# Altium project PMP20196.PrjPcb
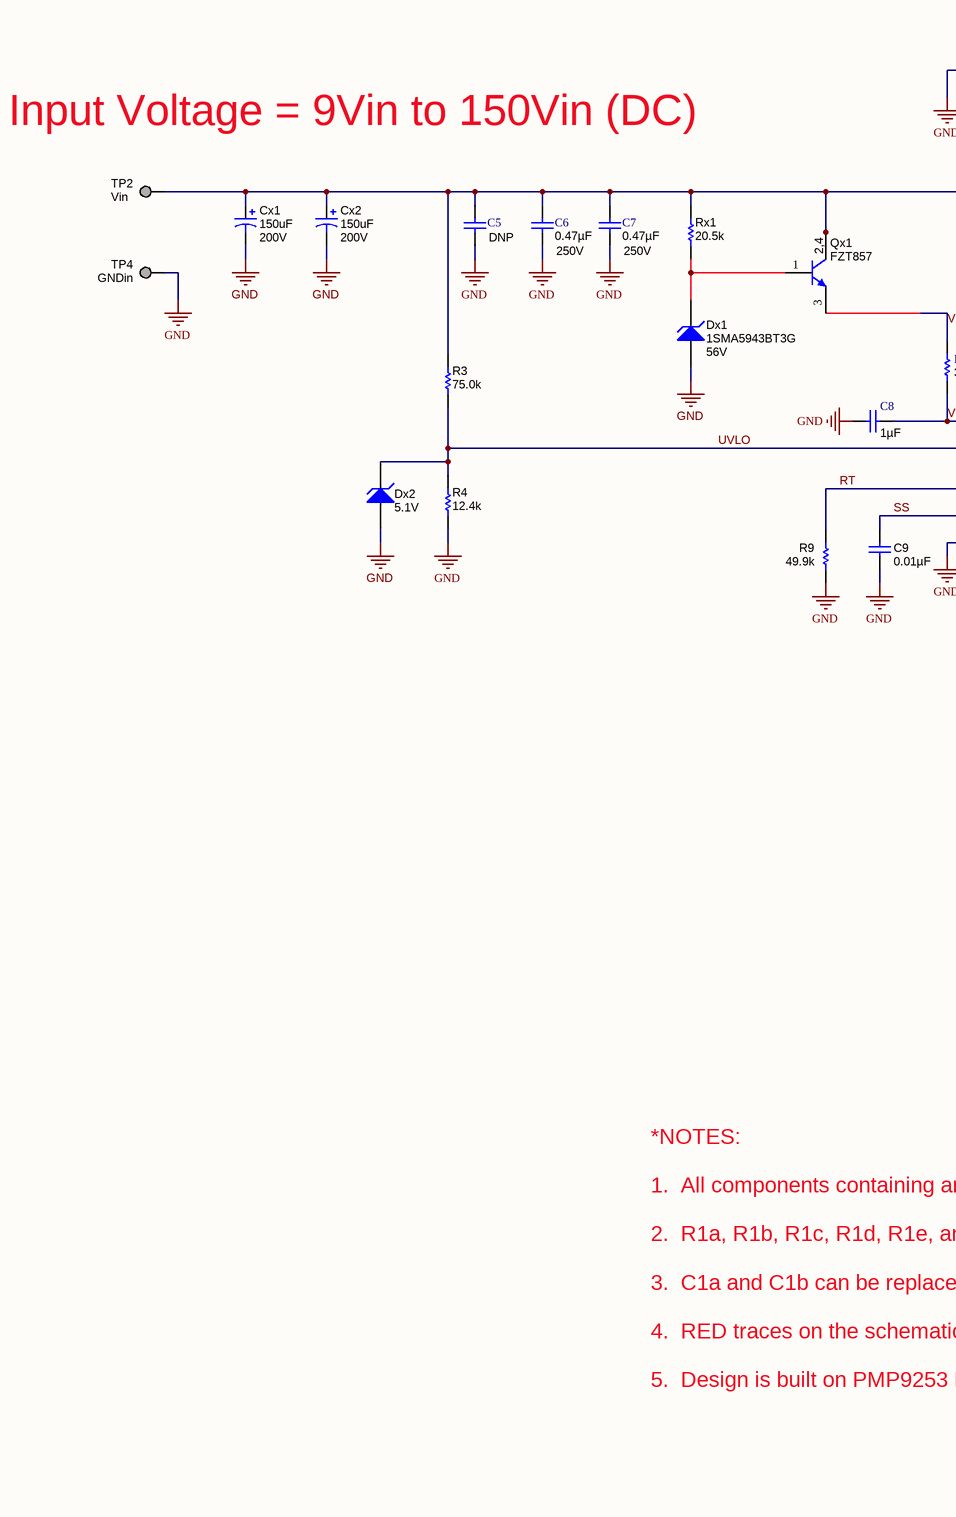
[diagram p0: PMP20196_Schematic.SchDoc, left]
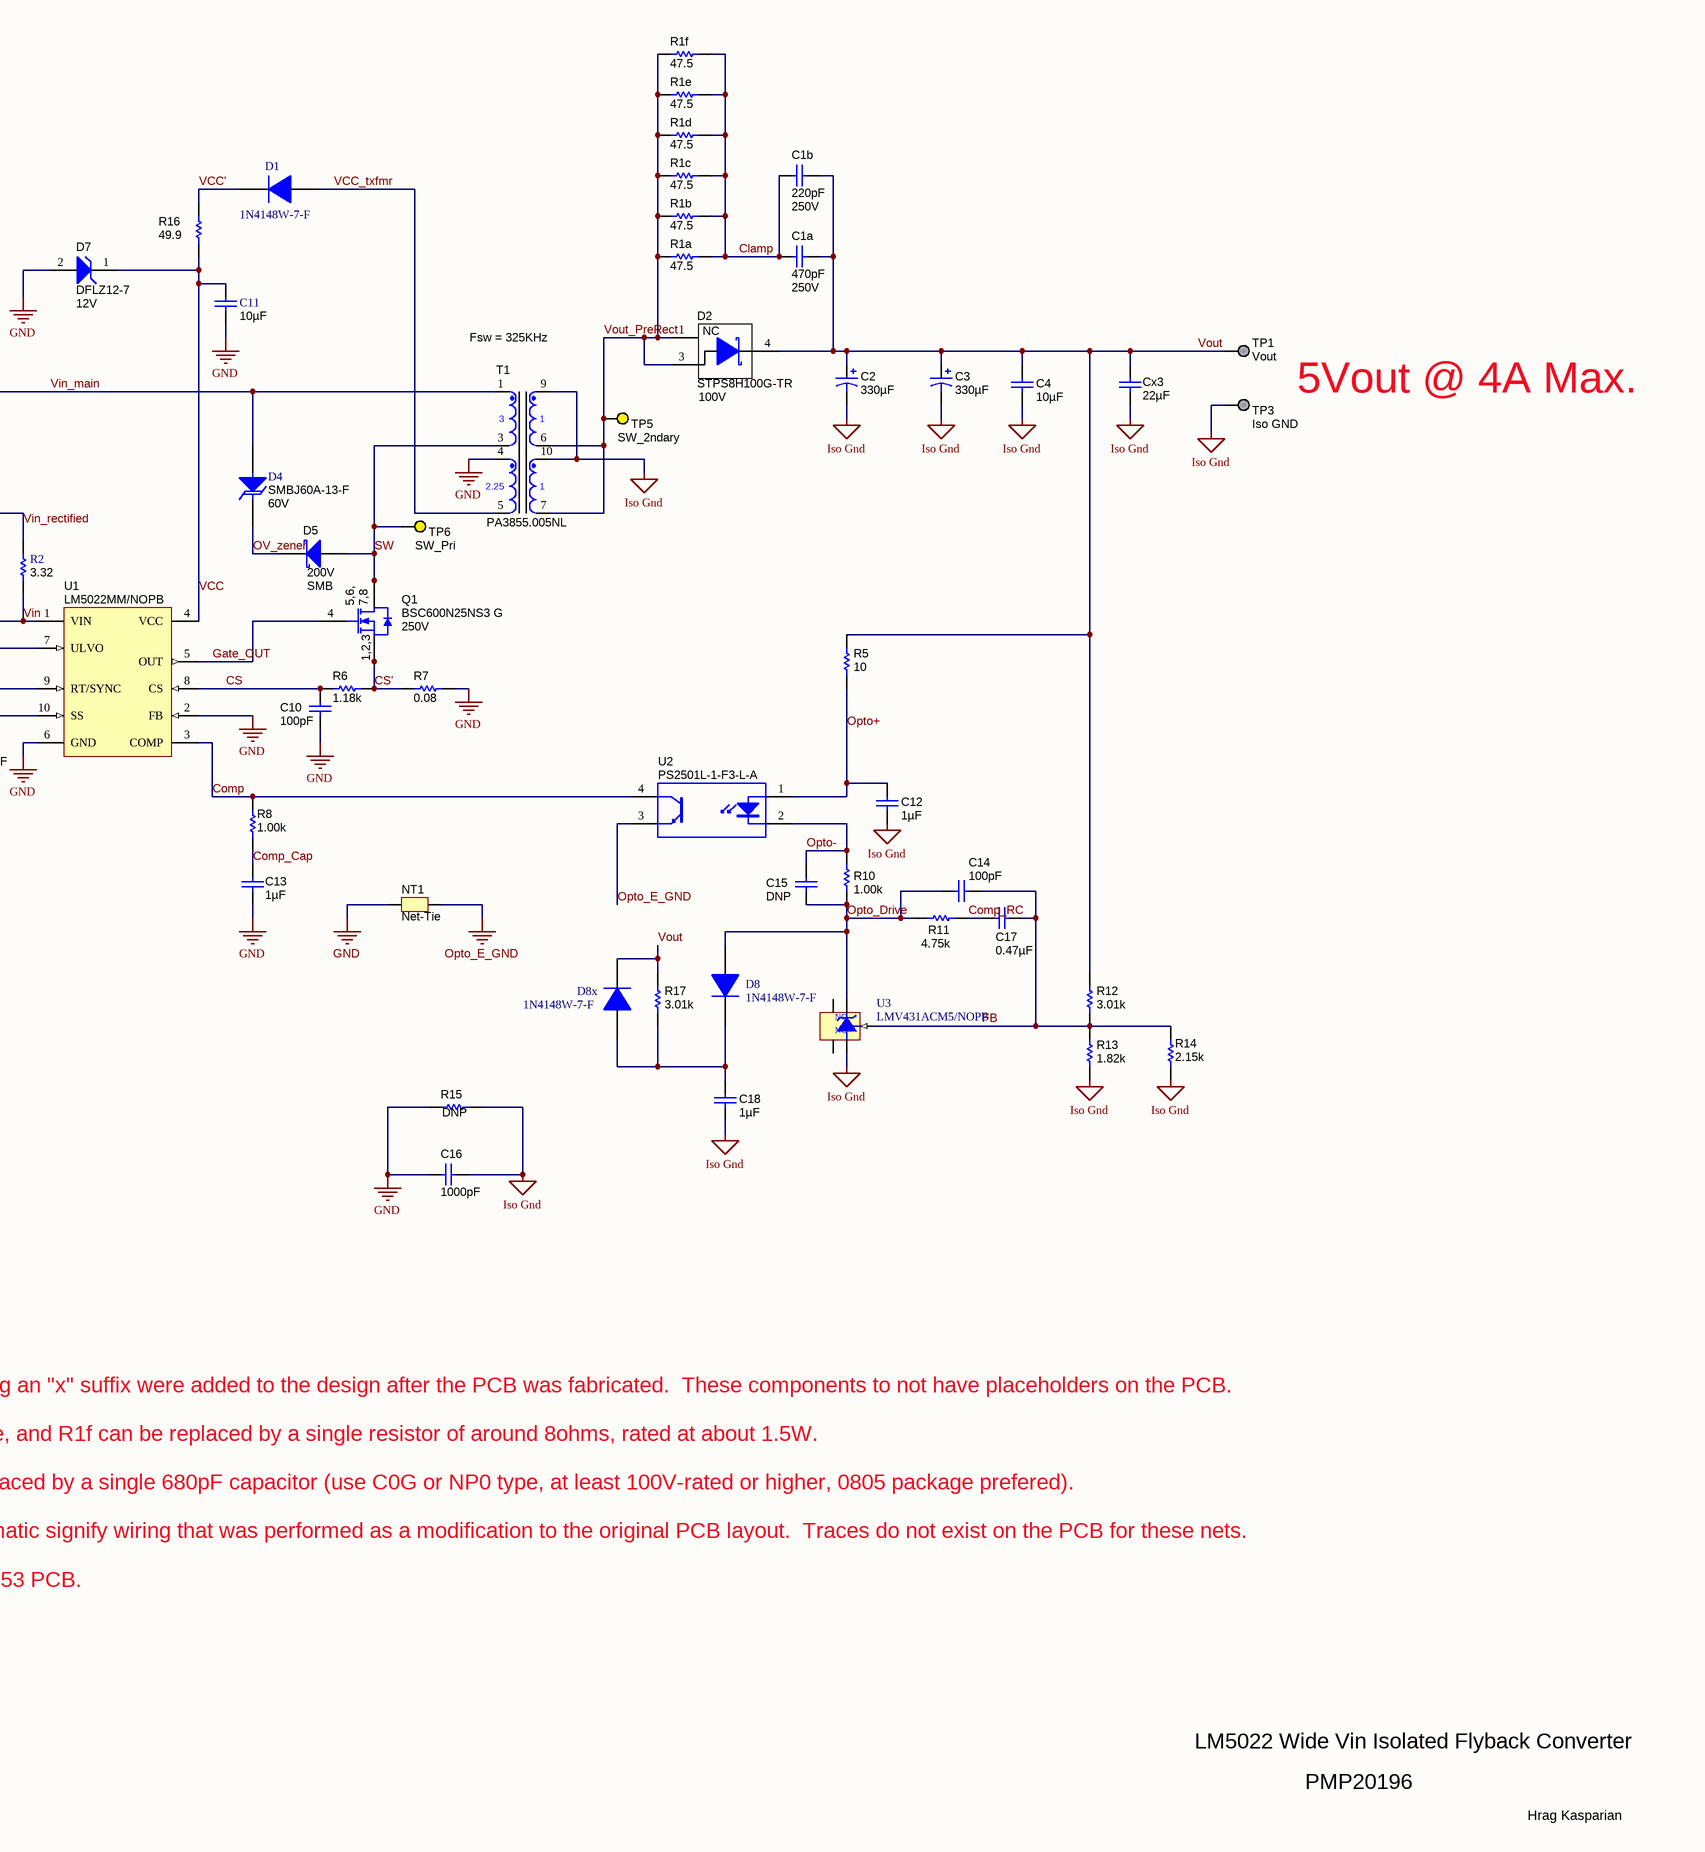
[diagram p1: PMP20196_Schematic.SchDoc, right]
TID: PMP20196; TechSupport: http://www.ti.com/support; SCH_Rev: A; PRJ_Title: LM5022 Isolated Flyback Converter; PRJ_Number: PMP20196; PRJ_Engineer: Hrag Kasparian; CopyrightYear: 2016
2 sheets, 82 parts. Net scope: global (net labels, ports and power ports of the same name join across sheets).
Board file: PMP9253.PcbDoc
Sheets:
  PMP20196_Schematic.SchDoc
  PMP20196_EVM_Hardware.SchDoc

## Sheet PMP20196_Schematic.SchDoc: Schematic
size C; DocumentNumber: 1; SheetNumber: 1; SheetTotal: 2; PageSetup: Record=PageOptions¦CenterHorizontal=True¦CenterVertical=True¦PrintScale=0.70¦XCorrection=1.00¦YCorrection=1.00¦PrintKind=1¦BorderSize=5000000¦LeftOffset=0¦BottomOffset=0¦Orientation=2¦PaperLength=1000¦PaperWidth=1000¦Scale=100¦PaperSource=15¦PrintQuality=600¦MediaType=1¦DitherType=10¦PaperKind=11x17¦PrintScaleMode=1

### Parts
C1a  value 470pF  Value1: 250V  [0603_HV]  (hidden comment: CGA3E3C0G2E471J)
C1b  value 220pF  Value1: 250V  [0603_HV]  (hidden comment: CGA3E3C0G2E471J)
C2  ValueDisplayed: 330µF  [SM_RADIAL_8MM]  (hidden comment: Santo, 10SVP330M)
C3  ValueDisplayed: 330µF  [SM_RADIAL_8MM]  (hidden comment: Santo, 10SVP330M)
C4  ValueDisplayed: 10µF  [0805_HV]  (hidden comment: GRM21BR71A106KE51L)
C5  DNP  [1812]
C6  ValueDisplayed: 0.47µF  Value2: 250V  [1812]  (hidden comment: GRM43DR72E474KW01L)
C7  ValueDisplayed: 0.47µF  Value2: 250V  [1812]  (hidden comment: GRM43DR72E474KW01L)
C8  ValueDisplayed: 1µF  [1206]  (hidden comment: C3216X7R2A105M)
C9  ValueDisplayed: 0.01µF  [0603]  (hidden comment: C1608C0G1E103J)
C10  ValueDisplayed: 100pF  [0603]  (hidden comment: 06035A101JAT2A)
C11  ValueDisplayed: 10µF  [1206]  (hidden comment: GRM31CR71E106KA12L)
C12  ValueDisplayed: 1µF  [0603]  (hidden comment: C1608X7R1C105K)
C13  ValueDisplayed: 1µF  [0603]  (hidden comment: C1608X7R1E105K080AB)
C14  ValueDisplayed: 100pF  [0603]  (hidden comment: 06033C101KAT2A)
C15  DNP  [0603]
C16  ValueDisplayed: 1000pF  [0805_HV]  (hidden comment: C2012C0G2E102J)
C17  ValueDisplayed: 0.47µF  [0603]  (hidden comment: GRM188R61A474KA61D)
C18  ValueDisplayed: 1µF  [0603]  (hidden comment: C1608X7R1C105K)
Cx1  value 150uF  Value1: 200V  [TBD]  (hidden comment: EEU-EE2D151)
Cx2  value 150uF  Value1: 200V  [TBD]  (hidden comment: EEU-EE2D151)
Cx3  ValueDisplayed: 22µF  [1210_280]  (hidden comment: CGA6P1X7R1C226M250AC)
D1  1N4148W-7-F  [SOD-123]
D2  STPS8H100G-TR  value 100V  [DDPAK]
D4  SMBJ60A-13-F  value 60V  [SMB]
D5  200V  [SMB]
D7  DFLZ12-7  value 12V  [powerDI123]
D8  1N4148W-7-F  [SOD-123]
D8x  1N4148W-7-F  [SOD-123]
Dx1  1SMA5943BT3G  value 56V  [SMA]
Dx2  value 5.1V  [TBD]  (hidden comment: DZ2J051M0L)
NT1  Net-Tie  [Net-Tie_10mil]  (net tie, no BOM)
Q1  BSC600N25NS3 G  value 250V  [PG-TDSON-8]
Qx1  FZT857  [SOT-223]
R1a  ValueDisplayed: 47.5  [1206]  (hidden comment: CRCW120647R5FKEA)
R1b  ValueDisplayed: 47.5  [1206]  (hidden comment: CRCW120647R5FKEA)
R1c  ValueDisplayed: 47.5  [1206]  (hidden comment: CRCW120647R5FKEA)
R1d  ValueDisplayed: 47.5  [1206]  (hidden comment: CRCW120647R5FKEA)
R1e  ValueDisplayed: 47.5  [1206]  (hidden comment: CRCW120647R5FKEA)
R1f  ValueDisplayed: 47.5  [1206]  (hidden comment: CRCW120647R5FKEA)
R2  value 3.32  [1206]  (hidden comment: CRCW12063R32FKEA)
R3  ValueDisplayed: 75.0k  [1206]  (hidden comment: CRCW120675K0FKEA)
R4  ValueDisplayed: 12.4k  [0603]  (hidden comment: CRCW060312K4FKEA)
R5  10  [0805_HV]
R6  ValueDisplayed: 1.18k  [0603]  (hidden comment: CRCW06031K18FKEA)
R7  ValueDisplayed: 0.08  [2512]  (hidden comment: CRA2512-FZ-R080ELF)
R8  value 1.00k  [0603]  (hidden comment: CRCW06031K00FKEA)
R9  value 49.9k  [0603]  (hidden comment: CRCW060349K9FKEA)
R10  value 1.00k  [0603]  (hidden comment: CRCW06031K00FKEA)
R11  value 4.75k  [0603]  (hidden comment: CRCW06034K75FKEA)
R12  value 3.01k  [0603]  (hidden comment: CRCW06033K01FKEA)
R13  value 1.82k  [0603]  (hidden comment: CRCW06031K82FKEA)
R14  ValueDisplayed: 2.15k  [0603]  (hidden comment: CRCW06032K15FKEA)
R15  DNP  [0805_HV]
R16  value 49.9  [1206]  (hidden comment: CRCW120649R9FKEA)
R17  value 3.01k  [0603]  (hidden comment: CRCW06033K01FKEA)
Rx1  ValueDisplayed: 20.5k  [2512]  (hidden comment: CRCW251220K5FKEG)
T1  PA3855.005NL  [PA3855.005NL]
TP1  Vout  [Keystone1503-2]
TP2  Vin  [Keystone1503-2]
TP3  Iso GND  [Keystone1503-2]
TP4  GNDin  [Keystone1503-2]
TP5  SW_2ndary  [Keystone5014]
TP6  SW_Pri  [Keystone5014]
U1  LM5022MM/NOPB  [MUB10A_N]
U2  PS2501L-1-F3-L-A  [PS2501L]
U3  LMV431ACM5/NOPB  [MF05A_N]

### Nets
GND: C5.2 C6.2 C7.2 C8.2 C9.2 C10.2 C11.2 C13.2 C16.2 Cx1.2(-) Cx2.2(-) D7.2(A) Dx1.2(A) Dx2.2(A) NT1.1 R4.1 R7.2 R9.1 R15.1 T1.4 TP4.1 U1.2(FB) U1.6(GND)
Iso Gnd: C2.2(-) C3.2(-) C4.2 C12.1 C16.1 C18.1 Cx3.1 R13.1 R14.1 R15.2 T1.9 T1.10 TP3.1 U3.5(A)
Opto_E_GND: NT1.2 U2.3(E)
Clamp: C1a.1 C1b.1 R1a.2 R1b.2 R1c.2 R1d.2 R1e.2 R1f.2
Comp: R8.2 U1.3(COMP) U2.4(C)
Comp_Cap: C13.1 R8.1
Comp_RC: C17.2 R11.2
CS: C10.1 R6.1 U1.8(CS)
CS': Q1.1(S) Q1.2(S) Q1.3(S) R6.2 R7.1
FB: C14.1 C17.1 R12.1 R13.2 R14.2 U3.4(REF)
Gate_OUT: Q1.4(G) U1.5(OUT)
Opto+: C12.2 R5.1 U2.1(A)
Opto-: C15.2 R10.2 U2.2(K)
Opto_Drive: C14.2 C15.1 D8.2(A) R10.1 R11.1 U3.3(K)
OV_zener: D4.1(K) D5.1(K)
RT: R9.2 U1.9(RT/SYNC)
SS: C9.1 U1.10(SS)
SW: D5.2(A) Q1.5(D) Q1.6(D) Q1.7(D) Q1.8(D) Q1.9(D) T1.3 TP6.1
UVLO: Dx2.1(K) R3.1 R4.2 U1.7(ULVO)
VCC: C11.1 D7.1(K) R16.1 U1.4(VCC)
VCC': D1.1(K) R16.2
VCC_txfmr: D1.2(A) T1.5
Vin: C8.1 R2.1 U1.1(VIN)
Vin_main: C5.1 C6.1 C7.1 Cx1.1(+) Cx2.1(+) D4.2(A) Qx1.2(C) Qx1.4(C) R3.2 Rx1.2 T1.1 TP2.1
Vin_rectified: Qx1.3(E) R2.2
Vout: C1a.2 C1b.2 C2.1(+) C3.1(+) C4.1 Cx3.2 D2.4(K) D8x.1(K) R5.2 R12.2 R17.2 TP1.1
Vout_PreRect: D2.1(NC) D2.3(A) R1a.1 R1b.1 R1c.1 R1d.1 R1e.1 R1f.1 T1.6 T1.7 TP5.1
NetC18_2: C18.2 D8.1(K) D8x.2(A) R17.1
NetDx1_1: Dx1.1(K) Qx1.1(B) Rx1.1

Not connected (* = marked no-connect by the designer): U3 1(NC) 2(NC)

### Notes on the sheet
- Input Voltage = 9Vin to 150Vin (DC)
- (near T1) Fsw = 325KHz
- 5Vout @ 4A Max.
- *NOTES:
  1.  All components containing an "x" suffix were added to the design after the PCB was fabricated.  These components to not have placeholders on the PCB.
  2.  R1a, R1b, R1c, R1d, R1e, and R1f can be replaced by a single resistor of around 8ohms, rated at about 1.5W.
  3.  C1a and C1b can be replaced by a single 680pF capacitor (use C0G or NP0 type, at least 100V-rated or higher, 0805 package prefered).
  4.  RED traces on the schematic signify wiring that was performed as a modification to the original PCB layout.  Traces do not exist on the PCB for these nets.
  5.  Design is built on PMP9253 PCB.
- LM5022 Wide Vin Isolated Flyback Converter
- PMP20196
- Hrag Kasparian

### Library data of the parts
C1a = Capacitor: CAP, CERM, 470pF, 250V, C0G, 5%, 0603; Manufacturer: TDK; Polarized: N; U/M: EA
C1b = Capacitor: CAP, CERM, 220pF, 250V, C0G, 5%, 0603; Manufacturer: TDK; Polarized: N; U/M: EA
C2 C3 = 10SVP330M: CAP, OS-CON, 330uF, 10V, +/-20%, 0.017 ohm, 8x10 SMD; Manufacturer: Sanyo; Polarized: Y; CompType: Capacitor; U/M: EA; Cap_F: 0.00033; Tolerance_%: 20; VDC_V: 10; ESR_Ohm: 0.017; IRMS_A: 3.95; TaMin_C: -55; TaMax_C: 105; Cap_Case: 8.3x8.3x11.9
C4 = GRM21BR71A106KE51L: CAP, CERM, 10uF, 10V, +/-10%, X7R, 0805; Manufacturer: MuRata; Polarized: N; CompType: Capacitor; U/M: EA; Cap_F: 0.00001; Tolerance_%: 10; ESR_Ohm: 0.003; Value1: 0.003 ohm; TaMin_C: -55; TaMax_C: 125; Cap_Case: 0805
C5 = GRM43DR72E474KW01L: CAP, CERM, 0.47 µF, 250 V, +/- 10%, X7R, 1812; Manufacturer: MuRata; Polarized: N; TaMax_C: 125; TaMin_C: -55; Tolerance_%: 10; VDC_V: 250; Cap_F: 0.00000047; CompType: Capacitor; Value: 0.47uF; ValueDisplayed: 0.47µF; U/M: EA; Value1: Unknown; Value2: 250V; AEC Category: Q200
C6 C7 = GRM43DR72E474KW01L: CAP, CERM, 0.47 µF, 250 V, +/- 10%, X7R, 1812; Manufacturer: MuRata; Polarized: N; TaMax_C: 125; TaMin_C: -55; Tolerance_%: 10; VDC_V: 250; Cap_F: 0.00000047; CompType: Capacitor; Value: 0.47uF; U/M: EA; Value1: Unknown; AEC Category: Q200
C8 = C3216X7R2A105M: CAP, CERM, 1uF, 100V, +/-20%, C Series, 1206; Manufacturer: TDK; ESR_Ohm: 0.006; IRMS_A: 4.5; Polarized: N; TaMax_C: 125; TaMin_C: -55; Tolerance_%: 20; VDC_V: 100; Cap_F: 0.000001; CompType: Capacitor; U/M: EA; Value1: 0.006 ohm
C9 = C1608C0G1E103J: CAP, CERM, 0.01uF, 25V, +/-5%, C0G/NP0, 0603; Manufacturer: TDK; Polarized: N; CompType: Capacitor; U/M: EA; Cap_F: 0.00000001; Tolerance_%: 5; Value1: Unknown; VDC_V: 25; TaMin_C: -55; TaMax_C: 125
C10 = 06035A101JAT2A: CAP, CERM, 100pF, 50V, +/-5%, C0G/NP0, 0603; Manufacturer: AVX; Polarized: N; CompType: Capacitor; U/M: EA; Cap_F: 0.0000000001; Tolerance_%: 5; ESR_Ohm: 0.119; Value1: 0.119 ohm; VDC_V: 50; TaMin_C: -55; TaMax_C: 125
C11 = GRM31CR71E106KA12L: CAP, CERM, 10uF, 25V, +/-10%, X7R, 1206; Manufacturer: MuRata; Cap_Case: 2220; Polarized: N; TaMax_C: 125; TaMin_C: -55; Tolerance_%: 10; VDC_V: 25; Cap_F: 0.00001; CompType: Capacitor; U/M: EA; Value1: Unknown
C12 C18 = C1608X7R1C105K: CAP, CERM, 1uF, 16V, +/-10%, X7R, 0603; Manufacturer: TDK; Polarized: N; CompType: Capacitor; U/M: EA; Cap_F: 0.000001; Tolerance_%: 10; ESR_Ohm: 0.0057; Value1: 0.0057 ohm; VDC_V: 16; TaMin_C: -55; TaMax_C: 125
C13 = C1608X7R1E105K080AB: CAP, CERM, 1uF, 25V, +/-10%, X7R, 0603; Manufacturer: TDK; Polarized: N; CompType: Capacitor; U/M: EA; Cap_F: 0.000001; Tolerance_%: 10; Value1: Unknown; VDC_V: 25; TaMin_C: -55; TaMax_C: 125
C14 = 06033C101KAT2A: CAP, CERM, 100pF, 25V, +/-10%, X7R, 0603; Manufacturer: AVX; Polarized: N; CompType: Capacitor; U/M: EA; Cap_F: 0.0000000001; Tolerance_%: 10; Value1: Unknown; VDC_V: 25; TaMin_C: -55; TaMax_C: 125
C15 = C1608X7R1C105K: CAP, CERM, 1uF, 16V, +/-10%, X7R, 0603; Manufacturer: TDK; Polarized: N; CompType: Capacitor; ValueDisplayed: 1µF; U/M: EA; Cap_F: 0.000001; Tolerance_%: 10; ESR_Ohm: 0.0057; Value1: 0.0057 ohm; VDC_V: 16; TaMin_C: -55; TaMax_C: 125
C16 = C2012C0G2E102J: CAP, CERM, 1000pF, 250V, +/-5%, C0G/NP0, 0805; Manufacturer: TDK; Polarized: N; CompType: Capacitor; U/M: EA; Cap_F: 0.000000001; Tolerance_%: 5; ESR_Ohm: 0.0408; Value1: 0.0408 ohm; VDC_V: 250; TaMin_C: -55; TaMax_C: 125; Cap_Case: 0805
C17 = GRM188R61A474KA61D: CAP, CERM, 0.47uF, 10V, +/-10%, X5R, 0603; Manufacturer: MuRata; Polarized: N; CompType: Capacitor; U/M: EA; Cap_F: 0.00000047; Tolerance_%: 10; Value1: Unknown; TaMin_C: -55; TaMax_C: 85
Cx1 Cx2 = Capacitor_Polarized: CAP, Al Electrolytic, 150uF, 200V, +/-20%, 1.86Arms, TH; Manufacturer: Panasonic; Polarized: Y; U/M: EA
Cx3 = CGA6P1X7R1C226M250AC: CAP, CERM, 22 µF, 16 V, +/- 20%, X7R, AEC-Q200 Grade 1, 1210; Manufacturer: TDK; Polarized: N; CompType: Capacitor; Value: 22uF; U/M: EA; Cap_F: 0.000022; Tolerance_%: 20; Value1: Unknown; VDC_V: 16; Value2: 16V; TaMin_C: -55; TaMax_C: 125; Cap_Case: 1210; AEC Category: Q200; AEC Qualified: Y; AEC Grade: 1
D1 D8 D8x = 1N4148W-7-F: Diode, Ultrafast, 100V, 0.15A, SOD-123; Manufacturer: Diodes Inc.; U/M: EA; Vf_V: 1.25; Io_A: 0.15; Vr_V: 100; TJmax_C: 150; Value: 1.25V
D2 = Diode_Schottky_A3C4: Diode, Schottky, 100V, 8A, D2PAK; Manufacturer: ST Microelectronics; U/M: EA
D4 = SMBJ60A-13-F: Diode, TVS, Uni, 60 V, 600 W, SMB; Manufacturer: Diodes Inc.; U/M: EA; Power_W: 5; Value1: 5W; Vr_V: 60; AEC Category: Q101
D5 = MBRS3200T3G: Diode, Schottky, 200 V, 3 A, SMB; Manufacturer: ON Semiconductor; U/M: EA; Vf_V: 0.84; Value1: 3A; Value2: 0.84V; Io_A: 3; Vr_V: 200; TJmax_C: 175; RJC_CperW: 62; AEC Category: Q101
D7 = DFLZ12-7: Diode, Zener, 12V, 1W, PowerDI123; Manufacturer: Diodes Inc.; U/M: EA; Power_W: 1; Vz_V: 12; RJA_CperW: 110
Dx1 = Zener: Diode, Zener, 56V, 1.5W, SMA; Manufacturer: ON Semi; SymbolCreator: a0412235; U/M: EA
Dx2 = Zener: Diode, Zener, 5.1V, 200mW, +/-5%, SOD-323F; Manufacturer: Panasonic; SymbolCreator: a0412235; U/M: EA
NT1 = Net-Tie: Single point connection between nets.; SymbolCreator: codlsc
Q1 = BSC600N25NS3 G: MOSFET, N-CH, 250 V, 25 A, PG-TDSON-8; Manufacturer: Infineon Technologies; Alternate Manufacturer: None; U/M: EA; ChType: N; VdsMax_V: 250; Value1: 0.06 ohm; Rdson45_ohm: 0.06; Value2: 22 nC; QgTyp_nC: 22; Vgs_V: 20; IdsMax_A: 25; AEC Category: Q101
Qx1 = FZT857, Zetex: Transistor, NPN, 300 V, 3.5 A, SOT-223; Manufacturer: Zetex; SymbolCreator: a0412235; PNP: 0; NPN: 1; Vceo_V: 300; Vcesat1_V: 0.095; Value: 300 V; IcRated_A: 3.5; Value1: 3.5 A; HfeMax: 200; TaMin_C: -55; TaMax_C: 150; CompType: BJT; U/M: EA; AEC Category: Q101
R1a R1b R1c R1d R1e R1f = CRCW120647R5FKEA: RES, 47.5, 1%, 0.25 W, 1206; Manufacturer: Vishay-Dale; CompType: Resistor; Value: 47.5; Value_Code: 47R5; Tolerance_%: 1; Power_W: 0.25; Value2: 0.25W; VDC_V: 200; TempCo: 100 ppm/C; EIA_Code: E96; U/M: EA; AEC Category: Q200
R2 = CRCW12063R32FKEA: RES, 3.32 ohm, 1%, 0.25W, 1206; Manufacturer: Vishay-Dale; CompType: Resistor; Tolerance_%: 1; VDC_V: 200; Power_W: 0.25; Value_Code: 3R32; TempCo_ppm/C: 100; EIA_Code: E96; U/M: EA
R3 = CRCW120675K0FKEA: RES, 75.0 k, 1%, 0.25 W, 1206; Manufacturer: Vishay-Dale; CompType: Resistor; Value: 75.0k; Res_ohm: 75000; Value_Code: 75k0; Tolerance_%: 1; Power_W: 0.25; Value2: 0.25W; VDC_V: 200; TempCo: 100 ppm/C; EIA_Code: E96; U/M: EA; AEC Category: Q200
R4 = CRCW060312K4FKEA: RES, 12.4 k, 1%, 0.1 W, 0603; Manufacturer: Vishay-Dale; CompType: Resistor; Value: 12.4k; Res_ohm: 12400; Value_Code: 12k4; Tolerance_%: 1; Power_W: 0.1; Value2: 0.1W; VDC_V: 75; TempCo: 100 ppm/C; EIA_Code: E96; U/M: EA; AEC Category: Q200
R5 = CRCW080510R0JNEA: RES, 10 ohm, 5%, 0.125W, 0805; Manufacturer: Vishay-Dale; CompType: Resistor; Value_Code: 10R0; Tolerance_%: 5; Power_W: 0.125; VDC_V: 150; TempCo: 200 ppm/C; EIA_Code: E24; U/M: EA
R6 = CRCW06031K18FKEA: RES, 1.18 k, 1%, 0.1 W, 0603; Manufacturer: Vishay-Dale; CompType: Resistor; Res_ohm: 1180; Value_Code: 1k18; Tolerance_%: 1; Power_W: 0.1; Value2: 0.1W; VDC_V: 75; TempCo: 100 ppm/C; EIA_Code: E96; U/M: EA; Value: 1.18k; AEC Category: Q200
R7 = CRA2512-FZ-R080ELF: RES, 0.08, 1%, 3 W, 2512; Manufacturer: Bourns; CompType: Resistor; Value: 0.08; U/M: EA; Value_Code: R080; Tolerance_%: 1; Power_W: 3; Value2: 3W; VDC_V: 0; TempCo: 75 ppm/C; AEC Category: Q200
R8 R10 = CRCW06031K00FKEA: RES, 1.00k ohm, 1%, 0.1W, 0603; Manufacturer: Vishay-Dale; CompType: Resistor; Res_ohm: 1000; Value_Code: 1k00; Tolerance_%: 1; Power_W: 0.1; VDC_V: 75; TempCo: 100 ppm/C; EIA_Code: E96; U/M: EA
R9 = CRCW060349K9FKEA: RES, 49.9k ohm, 1%, 0.1W, 0603; Manufacturer: Vishay-Dale; CompType: Resistor; Res_ohm: 49900; Value_Code: 49k9; Tolerance_%: 1; Power_W: 0.1; VDC_V: 75; TempCo: 100 ppm/C; EIA_Code: E96; U/M: EA
R11 = CRCW06034K75FKEA: RES, 4.75k ohm, 1%, 0.1W, 0603; Manufacturer: Vishay-Dale; CompType: Resistor; Res_ohm: 4750; Value_Code: 4k75; Tolerance_%: 1; Power_W: 0.1; VDC_V: 75; TempCo: 100 ppm/C; EIA_Code: E96; U/M: EA
R12 R17 = CRCW06033K01FKEA: RES, 3.01k ohm, 1%, 0.1W, 0603; Manufacturer: Vishay-Dale; CompType: Resistor; Res_ohm: 3010; Value_Code: 3k01; Tolerance_%: 1; Power_W: 0.1; VDC_V: 75; TempCo: 100 ppm/C; EIA_Code: E96; U/M: EA
R13 = CRCW06031K82FKEA: RES, 1.82k ohm, 1%, 0.1W, 0603; Manufacturer: Vishay-Dale; CompType: Resistor; Res_ohm: 1820; Value_Code: 1k82; Tolerance_%: 1; Power_W: 0.1; VDC_V: 75; TempCo: 100 ppm/C; EIA_Code: E96; U/M: EA
R14 = CRCW06032K15FKEA: RES, 2.15 k, 1%, 0.1 W, 0603; Manufacturer: Vishay-Dale; CompType: Resistor; Value: 2.15k; Res_ohm: 2150; Value_Code: 2k15; Tolerance_%: 1; Power_W: 0.1; Value2: 0.1W; VDC_V: 75; TempCo: 100 ppm/C; EIA_Code: E96; U/M: EA; AEC Category: Q200
R15 = CRCW08050000Z0EA: RES, 0 ohm, 5%, 0.125W, 0805; Manufacturer: Vishay-Dale; CompType: Resistor; Value: 0; Value_Code: 0000; Tolerance_%: 5; Power_W: 0.125; VDC_V: 150; TempCo: 200 ppm/C; EIA_Code: E24; U/M: EA
R16 = CRCW120649R9FKEA: RES, 49.9 ohm, 1%, 0.25W, 1206; Manufacturer: Vishay-Dale; CompType: Resistor; Value_Code: 49R9; Tolerance_%: 1; Power_W: 0.25; VDC_V: 200; TempCo: 100 ppm/C; EIA_Code: E96; U/M: EA
Rx1 = CRCW251220K5FKEG: RES, 20.5 k, 1%, 1 W, 2512; Manufacturer: Vishay-Dale; CompType: Resistor; Value: 20.5k; U/M: EA; Res_ohm: 20500; Value_Code: 20k5; Tolerance_%: 1; Value2: 1W; VDC_V: 500; TempCo: 100 ppm/C; EIA_Code: E96; AEC Category: Q200
T1 = PA3855.005NL: 3:2.25:1:1 Transformer; 21uH Primary Inductance; Manufacturer: Pulse Electronics; SymbolCreator: x0165573; CompType: Flyback Transformer; U/M: EA, IN, or GM
TP1-TP4 = 1503-2: Terminal, Turret, TH, Double; Manufacturer: Keystone; CompType: Turret Terminal; U/M: EA
TP5 TP6 = 5014: Test Point, Multipurpose, Yellow, TH; Manufacturer: Keystone; CompType: Test Point Loop; U/M: EA
U1 = LM5022MM/NOPB: 60V Low Side Controller for Boost and SEPIC, 10-pin MSOP, Pb-Free; Manufacturer: Texas Instruments; PackageTopMarking: ZXTT*5022; PowerWise: Y; CompType: Switcher
U2 = PS2501L-1-E3-L-A: Optocoupler, 5 kV, 200-400% CTR, SMT; Manufacturer: California Eastern Laboratories; SymbolCreator: a0412235; CTR (Min): 200%; CTR (Max): 400%; Voltage_Isolation_Vrms: 5000V
U3 = LMV431ACM5/NOPB: Low-Voltage (1.24V) Adjustable Precision Shunt Regulators, 5-pin SOT-23, Pb-Free; Manufacturer: Texas Instruments; PackageTopMarking: N09A*XTT; PowerWise: N; CompType: MiscPower

## Sheet PMP20196_EVM_Hardware.SchDoc: Hardware
size 431 x 279 mm; Date: Not shown in title block; ApprovedBy: Not shown in title block; CheckedBy: Not shown in title block; Author: Not shown in title block; CompanyName: Not shown in title block; Engineer: Not shown in title block; Organization: Not shown in title block; Address1: Not shown in title block; Address2: Not shown in title block; Address3: Not shown in title block; Address4: Not shown in title block; DocumentNumber: 2; Revision: Use project parameter SCH_Rev; SheetNumber: 2; SheetTotal: 2; PageSetup: Record=PageOptions¦CenterHorizontal=True¦CenterVertical=True¦PrintScale=1.00¦XCorrection=1.00¦YCorrection=1.00¦PrintKind=0¦BorderSize=5000000¦LeftOffset=0¦BottomOffset=0¦Orientation=2¦PaperLength=1000¦PaperWidth=1000¦Scale=100¦PaperSource=15¦PrintQuality=600¦MediaType=1¦DitherType=10¦PaperKind=Letter¦PrintScaleMode=1
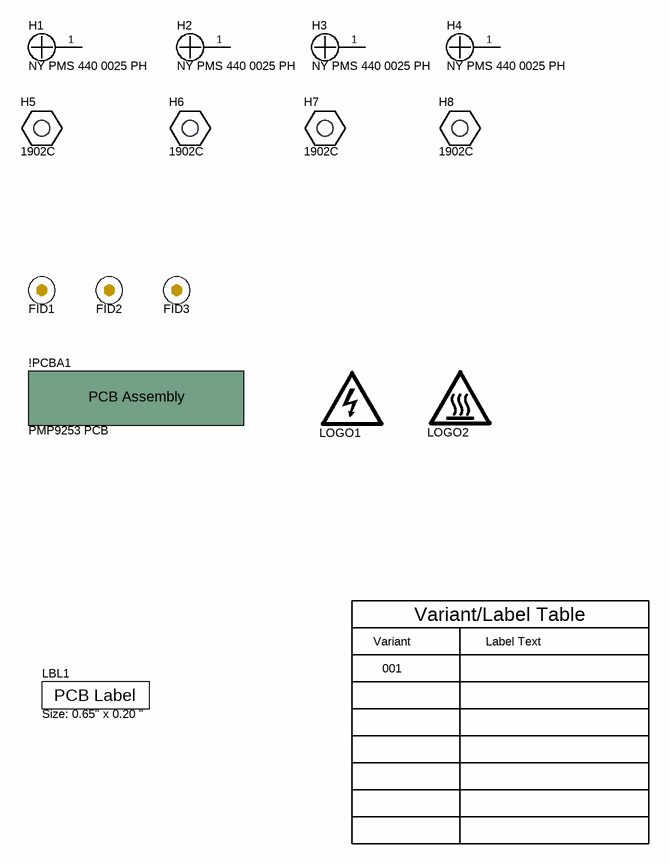
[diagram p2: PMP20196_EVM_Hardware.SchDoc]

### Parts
!PCBA1  PMP9253 PCB  (mechanical)
FID1  Fiducial  [Fiducial10-20]  (value not drawn)
FID2  Fiducial  [Fiducial10-20]  (value not drawn)
FID3  Fiducial  [Fiducial10-20]  (value not drawn)
H1  NY PMS 440 0025 PH  [NY PMS 440 0025 PH]
H2  NY PMS 440 0025 PH  [NY PMS 440 0025 PH]
H3  NY PMS 440 0025 PH  [NY PMS 440 0025 PH]
H4  NY PMS 440 0025 PH  [NY PMS 440 0025 PH]
H5  1902C  [Keystone_1902C]
H6  1902C  [Keystone_1902C]
H7  1902C  [Keystone_1902C]
H8  1902C  [Keystone_1902C]
LBL1  Size: 0.65" x 0.20 "  [Label_650x200]
LOGO1  DANGER HIGH VOLTAGE  [IEC_HighVoltage_Large]  (value not drawn)  (no BOM)
LOGO2  CAUTION HOT SURFACE  [IEC_HotSurface_Large]  (value not drawn)  (no BOM)

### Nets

Not connected (* = marked no-connect by the designer): H1 1; H2 1; H3 1; H4 1

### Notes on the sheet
- Variant
- Variant/Label Table
- Label Text
- 001

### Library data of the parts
!PCBA1 = PCBA: Manufacturer: Any; SymbolCreator: a0412235; U/M: EA
FID1-FID3 = Fiducial: Fiducial mark.  There is nothing to buy or mount.; SymbolCreator: codlsc
H1-H4 = NY PMS 440 0025 PH: Machine Screw, Round, #4-40 x 1/4, Nylon, Philips panhead; Manufacturer: B&F Fastener Supply; CompType: Hardware; SymbolCreator: codlsc; U/M: EA
H5-H8 = 1902C: Standoff, Hex, 0.5"L #4-40 Nylon; Manufacturer: Keystone; CompType: Hardware
LBL1 = THT-14-423-10: Thermal Transfer Printable Labels, 0.650" W x 0.200" H - 10,000 per roll; Manufacturer: Brady; SymbolCreator: a0412235; CompType: Label
LOGO1 = IEC_HighVoltage: IEC 61010-1 High Voltage Warning; SymbolCreator: a0412235
LOGO2 = IEC_HotSurface: IEC 61010-1 Hot Surface Warning; SymbolCreator: a0412235

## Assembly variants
001: not fitted C5 C15 FID1 FID2 FID3 R15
